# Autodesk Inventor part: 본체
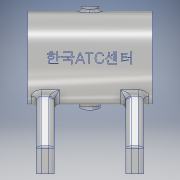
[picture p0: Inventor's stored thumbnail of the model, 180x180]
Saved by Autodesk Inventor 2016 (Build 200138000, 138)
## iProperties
Created: 2018-05
Part Number: 본체
Material: 알루미늄 6061
Document SubType Name: Modeling
Designer: USER
Mass: 318.264 g
Surface Area: 376.74 cm^2
Volume: 117.875 cm^3
Density: 2.7 g/cm^3
Appearance: 알루미늄 - 평지
Author: USER
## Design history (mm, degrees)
sketch "스케치1"
  geometry: L1 (-35, 0)-(35, 0); L2 (-35, 16)-(-35, 26); L3 (-35, 26)-(35, 26); L4 (35, 26)-(35, 16); L5 (35, 16)-(23, 16); L6 (23, 16)-(23, 14); L7 (23, 14)-(21, 14); L8 (21, 14)-(21, 21); L9 (21, 21)-(-21, 21); L10 (-21, 21)-(-21, 14); L11 (-21, 14)-(-23, 14); L12 (-23, 14)-(-23, 16); L13 (-23, 16)-(-35, 16); 2 further points
  constraints: 26 end point, 10 perpendicular, 2 point on line, 2 vertical alignment, 1 coincident, 1 horizontal, 1 midpoint, 1 vertical
  dimensions: "d0" = 70 distance of L1.start L1.end; "d1" = 42 diameter of L9 L1; "d2" = 52 diameter of L3 L1; "d3" = 32 diameter of L13 L1; "d4" = 28 diameter of L11 L1; "d6" = 42 distance of L8.end L9.end; "d7" = 2 distance of L10.end L11.end; "d8" = 2 distance of L6.end L7.end; "d9" = 12 distance of L12.end L2.start; "d74" = 32 diameter of L5 L1
revolve "회전1" sketch "스케치1" stored, may be unused: angle "d10" = 90 deg
node "작업 평면2"
  node "작업 평면1"
sketch "스케치2"
  geometry: L1 (0, 0)-(-65, 0); L2 (-65, 35)-(-65, -35); L3 (-65, 35)-(-50, 35); L4 (-50, 35)-(-19.386, 17.325); L5 (-50, 35)-(-3.646, 35); L6 (-50, -35)-(-19.386, -17.325); L7 (-65, -35)-(-50, -35); A1 r 26 centre (0, 0) between (-19.386, 17.325) and (-19.386, -17.325); 1 further point
  constraints: 14 end point, 4 horizontal, 2 point on circle, 2 symmetric about line, 1 centre point, 1 coincident, 1 midpoint, 1 vertical, 2 other
  dimensions: "d12" = 65 distance of L1.end L1.start; "d13" = 70 distance of L2.start L2.end; "d14" = 15 distance of L2.start L3.end; "d15" = 30 deg angle of L4 L5
extrude "돌출1" join sketch "스케치2" distance "d16" = 10; taper "d17" = 0 deg
sketch "스케치3"
  geometry: L1 (0, 0)-(10, 0) reference; L2 (10, 70)-(10, 0) reference; L3 (0, 70)-(10, 70) reference; L4 (10, 17.675)-(10, 52.325) reference; L5 (10, 35)-(0, 35); L6 (0, 70)-(0, 0) reference; 3 further points
  constraints: 2 end point, 1 midpoint, 1 symmetric about line
  dimensions: "d18" = 20 distance from line of point (5, 15) L5
hole "구멍1" sketch "스케치3" at (5, 15), (5, 55) diameter "d19" = 4.134; stored, may be unused: countersink angle "d23" = 90 deg, drill point angle "d25" = 118 deg; dims "d20" = 8, "d21" = 4, "d22" = 2, "d24" = 10
sketch "스케치4"
  geometry: C1 r 21 at (0, 0); 2 further points
  constraints: 1 centre point, 1 coincident
  dimensions: "d26" = 42 diameter of C1; "d27" = 21 distance of point (0, 0) point (-21, 0)
hole "구멍2" sketch "스케치4" at (-21, 0) diameter "d28" = 3.242; stored, may be unused: countersink angle "d32" = 90 deg, drill point angle "d34" = 118 deg; dims "d29" = 8, "d30" = 4, "d31" = 2, "d33" = 10
node "작업 평면5"
sketch "스케치7"
  geometry: L1 (0, 0)-(-50.719, 0); L2 (0, 0)-(-27.251, -9.919)
  constraints: 4 end point, 1 horizontal
  dimensions: "d49" = 20 deg angle of L2 L1; "d50" = 29 distance of L1.start L2.end
node "작업 평면6"
sketch "스케치8"
  geometry: C1 r 6 at (0, 0); 1 further point
  constraints: 1 centre point, 1 coincident
  dimensions: "d51" = 12 diameter of C1
extrude "돌출3" join sketch "스케치8" stored distance "d52" = 10; taper "d53" = 0 deg
sketch "스케치9"
  geometry: 1 further point
hole "구멍4" sketch "스케치9" at (0, 0) diameter "d54" = 4.917; stored, may be unused: countersink angle "d58" = 90 deg, drill point angle "d60" = 118 deg; dims "d55" = 30, "d56" = 4, "d57" = 2, "d59" = 35
fillet "모깎기1" dims "d61" = 0.3
fillet "모깎기2" dims "d62" = 3
fillet "모깎기3" dims "d63" = 2
chamfer "모따기1" distance "d64" = 1; stored, may be unused: second distance "d65" = 2, angle "d66" = 45 deg
fillet "모깎기4" dims "d67" = 3
fillet "모깎기5" dims "d68" = 3
node "작업 평면7"
sketch "스케치10"
  geometry: L1 (-35, 26)-(-35, -26) reference; 2 further points
  constraints: 1 other
  dimensions: "d70" = 35 distance from line of L1 point (0, 0); "d71" = 26 vertical distance of L1.start point (0, 0)
feature "엠보싱1" sketch "스케치10" dims "d0" = 70, "d1" = 42, "d2" = 52, "d3" = 32, "d4" = 28, "d6" = 42, "d7" = 2, "d8" = 2, "d9" = 12, "d72" = 0.5, "d73" = 0, "d74" = 32
node "작업 평면9"
  node "작업 평면8"
sketch "스케치13"
  geometry: C1 r 5 at (0, 0); 1 further point
  constraints: 1 centre point, 1 coincident
  dimensions: "d77" = 10 diameter of C1
extrude "돌출4" join sketch "스케치13" stored distance "d78" = 10; taper "d79" = 0 deg
sketch "스케치14"
  geometry: 1 further point
hole "구멍5" sketch "스케치14" at (0, 0) diameter "d80" = 5.188; stored, may be unused: countersink angle "d84" = 90 deg, drill point angle "d86" = 118 deg; dims "d81" = 35, "d82" = 4, "d83" = 2, "d85" = 35
fillet "모깎기6" dims "d87" = 2
fillet "모깎기7" dims "d88" = 3
node "솔리드1"
mirror "대칭1"
pattern_circular "원형 패턴1" dims angle "d36" = 360 deg
mirror "대칭2"
node "투영된 루프1"
other parameters: "d69" = 61.5, "d75" = 26, "d76" = 3
